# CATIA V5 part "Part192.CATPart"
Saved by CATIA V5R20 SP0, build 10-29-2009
Part number: FA 168700-2 comprimido
Revision: ANY
Definition: UNKNOWN
Nomenclature: FA 168700-2 comprimido
Source: Unknown
Bounding box of the stored display mesh (mm): x -2.8 to 2.8, y 0 to 4.04, z -2.8 to 2.8
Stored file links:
  C:\Users\Utente\Desktop\IO LAVORO\3D X SITO CF\CUMSA\3D files FA\FA 168700\Part192.CATPart
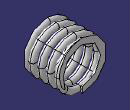
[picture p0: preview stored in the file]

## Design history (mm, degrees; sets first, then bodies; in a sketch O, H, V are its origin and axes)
Body1 "Cortar-Extruir1" (main body)
  Solid1: solid without history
